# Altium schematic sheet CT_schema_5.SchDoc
size 421 x 246 mm
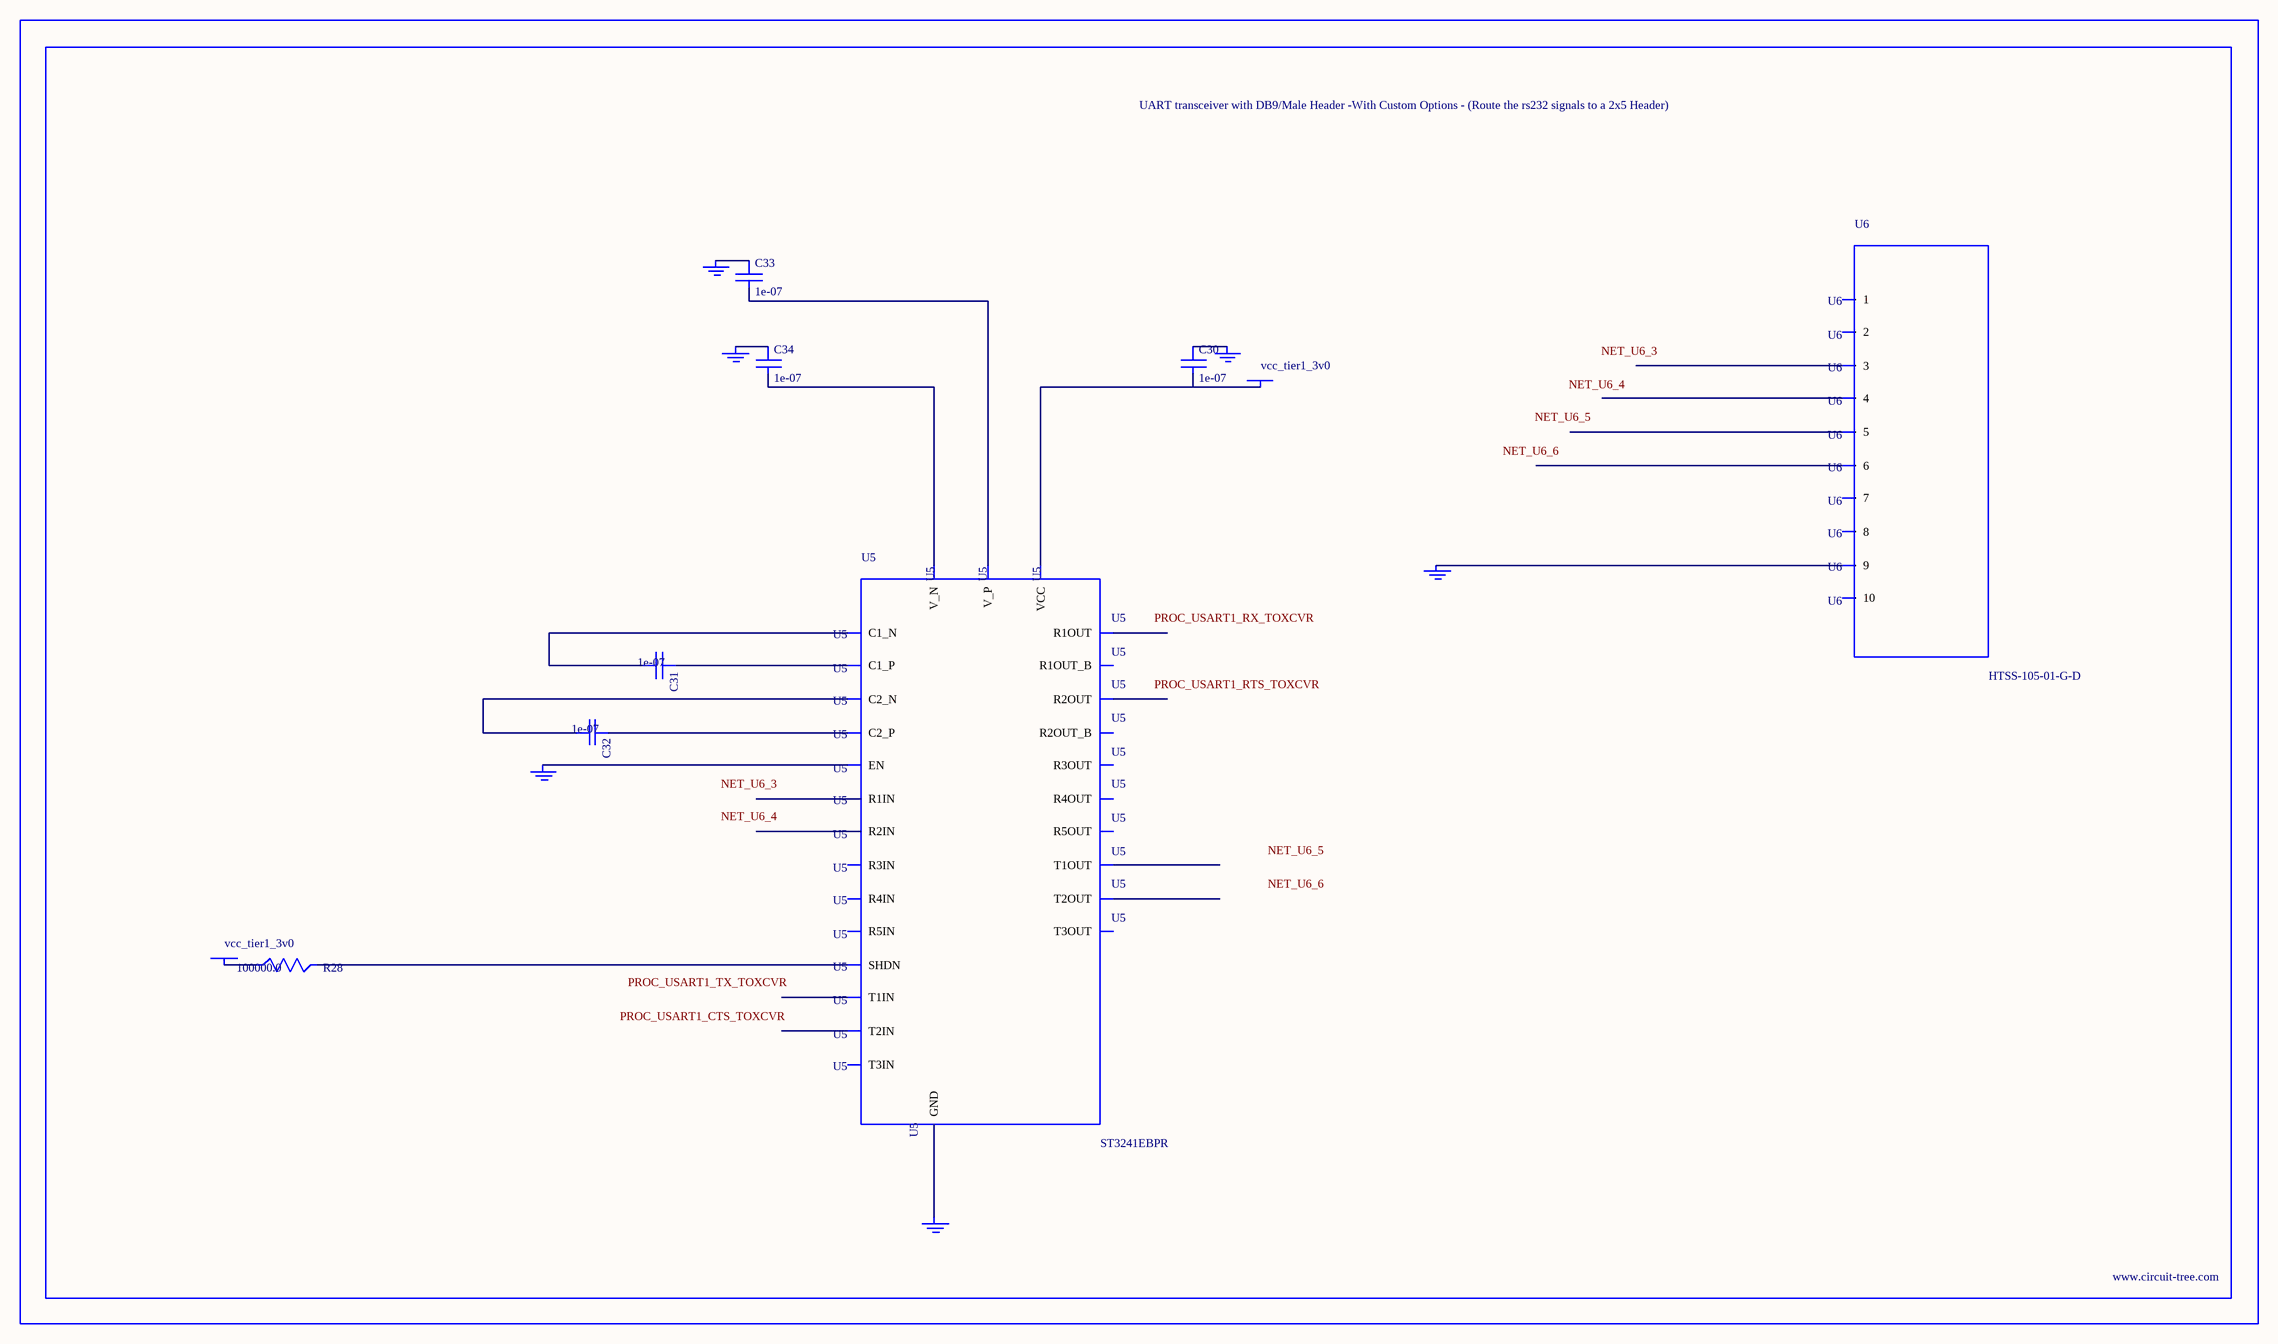
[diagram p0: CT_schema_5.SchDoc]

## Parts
BORDER4  (no value)
C30  1e-07  [C0402]
C31  1e-07  [C0402]
C32  1e-07  [C0402]
C33  1e-07  [C0402]
C34  1e-07  [C0402]
GND_INSTANCE_4_0  (no value)
GND_INSTANCE_4_1  (no value)
GND_INSTANCE_4_2  (no value)
GND_INSTANCE_4_3  (no value)
GND_INSTANCE_4_4  (no value)
GND_INSTANCE_4_5  (no value)
POWER_INSTANCE_4_0  vcc_tier1_3v0
POWER_INSTANCE_4_1  vcc_tier1_3v0
R28  100000.0  [R0603]
U5  ST3241EBPR  [SSOP-28]
U6  HTSS-105-01-G-D  [HTSS-105-01-G-D]

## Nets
NetC30_1: C30.1 GND_INSTANCE_4_2.0(GND)
NetC30_2: C30.2 POWER_INSTANCE_4_1.0(PWR) U5.26(VCC)
NetC31_1: C31.1 U5.28(C1_P)
NetC31_2: C31.2 U5.24(C1_N)
NetC32_1: C32.1 U5.1(C2_P)
NetC32_2: C32.2 U5.2(C2_N)
NetC33_1: C33.1 GND_INSTANCE_4_3.0(GND)
NetC33_2: C33.2 U5.27(V_P)
NetC34_1: C34.1 GND_INSTANCE_4_0.0(GND)
NetC34_2: C34.2 U5.3(V_N)
NetGND_INSTANCE_4_1_0: GND_INSTANCE_4_1.0(GND) U5.23(EN)
NetGND_INSTANCE_4_4_0: GND_INSTANCE_4_4.0(GND) U5.25(GND)
NetGND_INSTANCE_4_5_0: GND_INSTANCE_4_5.0(GND) U6.9
NetPOWER_INSTANCE_4_0_0: POWER_INSTANCE_4_0.0(PWR) R28.1
NetR28_2: R28.2 U5.22(SHDN)

Not connected (* = marked no-connect by the designer): U5 4(R1IN) 5(R2IN) 6(R3IN) 7(R4IN) 8(R5IN) 9(T1OUT) 10(T2OUT) 11(T3OUT) 12(T3IN) 13(T2IN) 14(T1IN) 15(R5OUT) 16(R4OUT) 17(R3OUT) 18(R2OUT) 19(R1OUT) 20(R2OUT_B) 21(R1OUT_B); U6 1 2 3 4 5 6 7 8 10

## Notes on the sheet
- Labels drawn without touching a wire or pin: NET_U6_3, NET_U6_4, NET_U6_5, NET_U6_6, PROC_USART1_CTS_TOXCVR, PROC_USART1_RTS_TOXCVR, PROC_USART1_RX_TOXCVR, PROC_USART1_TX_TOXCVR

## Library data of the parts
BORDER4 = BORDER_PAGE4
C30-C34 = C0402C104K3RACTU
GND_INSTANCE_4_0-GND_INSTANCE_4_5 = GND
POWER_INSTANCE_4_0 POWER_INSTANCE_4_1 = PWR
R28 = RC0603JR-07100KL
